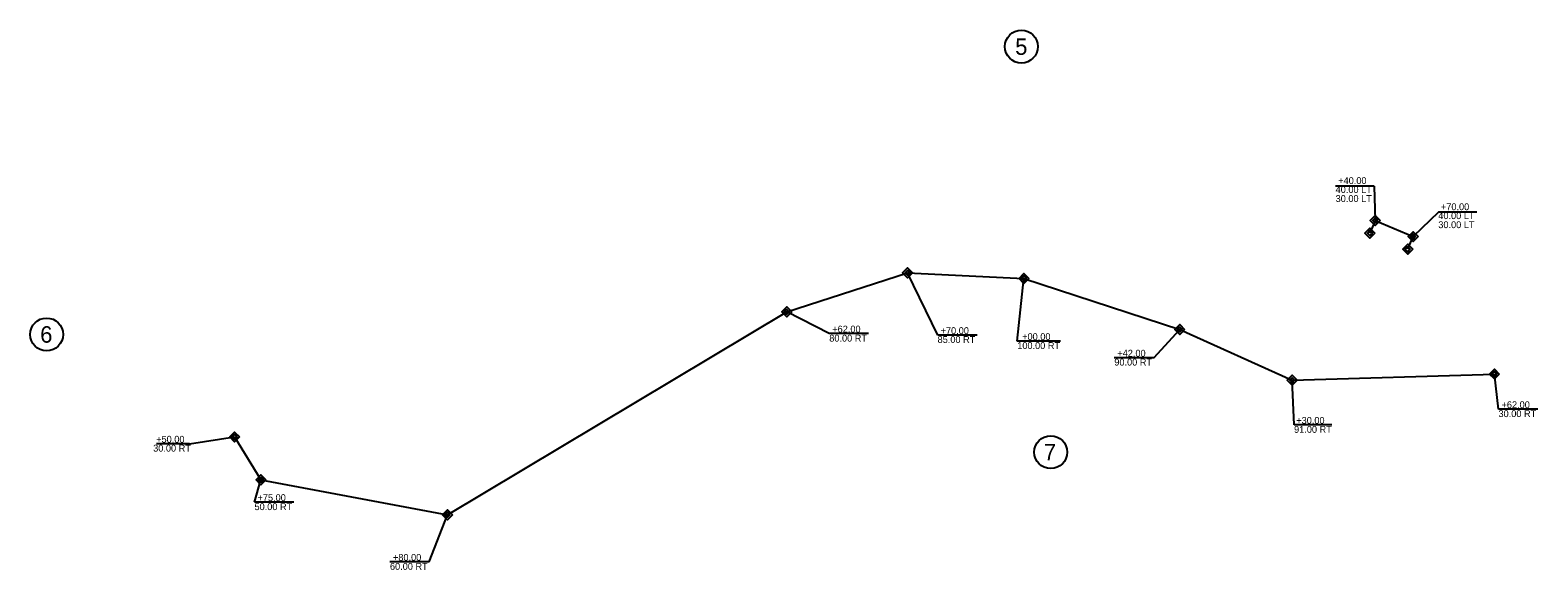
# Model space of a CAD drawing. Extents: x 1002576 to 1014655, y 551673 to 557994.
# Drawn here: x 1010654 to 1011753, y 551946 to 552340 of the extents above; entities that cross this region are included whole.
import ezdxf

# ---------------------------------------------------------------- set-up
doc = ezdxf.new("R2010")
doc.units = 0
for name, color, linetype in [('Exist Hydro Stream or Body of Water', 7, 'Continuous'), ('Exist Other Culture Area Outline', 7, 'Continuous'), ('Exist Roads EOP Other', 7, 'Continuous'), ('Exist Structure Major Deck Tunnel Box Culvert', 7, 'Continuous'), ('Exist Utilities Power Pole CELL', 7, 'Continuous')]:
    doc.layers.add(name, color=color, linetype=linetype)

msp = doc.modelspace()

# ---------------------------------------------------------------- linework, layer by layer
at = {"layer": 'Exist Hydro Stream or Body of Water'}
for p, q in [((1011634.9, 552201.4), (1011634.9, 552201.4)), ((1011631, 552192.2), (1011631, 552192.2)), ((1011662.5, 552189.6), (1011662.5, 552189.6)), ((1011658.6, 552180.4), (1011658.6, 552180.4)), ((1011293.8, 552163.2), (1011293.8, 552163.2)), ((1011378.7, 552159.1), (1011378.7, 552159.1)), ((1011205.7, 552134.7), (1011205.7, 552134.7)), ((1011492.3, 552121.8), (1011492.3, 552121.8)), ((1011574.3, 552084.8), (1011574.3, 552084.8)), ((1011721.8, 552089.3), (1011721.8, 552089.3)), ((1010803, 552043.4), (1010803, 552043.4)), ((1010822.2, 552012.1), (1010822.2, 552012.1)), ((1010958.2, 551986.6), (1010958.2, 551986.6))]:
    msp.add_line(p, q, dxfattribs=at)
at = {"layer": 'Exist Other Culture Area Outline'}
for p, q in [((1011634.9, 552201.4), (1011631, 552192.2)), ((1011634.9, 552201.4), (1011662.5, 552189.6)), ((1011658.6, 552180.4), (1011662.5, 552189.6)), ((1011205.7, 552134.7), (1011293.8, 552163.2)), ((1011293.8, 552163.2), (1011378.7, 552159.1)), ((1011378.7, 552159.1), (1011492.3, 552121.8)), ((1010958.2, 551986.6), (1011205.7, 552134.7)), ((1011492.3, 552121.8), (1011574.3, 552084.8)), ((1011574.3, 552084.8), (1011721.8, 552089.3)), ((1010803, 552043.4), (1010822.2, 552012.1)), ((1010822.2, 552012.1), (1010958.2, 551986.6))]:
    msp.add_line(p, q, dxfattribs=at)
at = {"layer": 'Exist Roads EOP Other'}
for p, q in [((1011634.1, 552226.5), (1011606, 552226.5)), ((1011709.1, 552207.4), (1011681, 552207.4)), ((1011265.4, 552118.8), (1011236.7, 552118.8)), ((1011344.5, 552117.8), (1011315.8, 552117.8)), ((1011405.3, 552113.3), (1011373.8, 552113.3)), ((1011473.3, 552101.2), (1011444.6, 552101.2)), ((1011753.5, 552063.7), (1011724.8, 552063.7)), ((1011603.2, 552052.2), (1011575.7, 552052.2)), ((1010770, 552038.4), (1010746, 552038.4)), ((1010846.2, 551995.8), (1010817.5, 551995.8)), ((1010945, 551952.2), (1010916.3, 551952.2))]:
    msp.add_line(p, q, dxfattribs=at)
for points in [[(1011634.1, 552226.5), (1011634.9, 552201.4)], [(1011681, 552207.4), (1011662.5, 552189.6)], [(1011315.8, 552117.8), (1011293.8, 552163.2)], [(1011373.8, 552113.3), (1011378.7, 552159.1)], [(1011236.7, 552118.8), (1011205.7, 552134.7)], [(1011473.3, 552101.2), (1011492.3, 552121.8)], [(1011575.7, 552052.2), (1011574.3, 552084.8)], [(1011724.8, 552063.7), (1011721.8, 552089.3)], [(1010770, 552038.4), (1010803, 552043.4)], [(1010817.5, 551995.8), (1010822.2, 552012.1)], [(1010945, 551952.2), (1010958.2, 551986.6)]]:
    msp.add_lwpolyline(points, dxfattribs=at)
at = {"layer": 'Exist Structure Major Deck Tunnel Box Culvert'}
for points in [[(1011638.5, 552201.4), (1011634.9, 552197.8), (1011631.3, 552201.4), (1011634.9, 552205)], [(1011634.6, 552192.2), (1011631, 552188.6), (1011627.4, 552192.2), (1011631, 552195.8)], [(1011636.7, 552201.4), (1011634.9, 552199.6), (1011633.1, 552201.4), (1011634.9, 552203.2)], [(1011632.8, 552192.2), (1011631, 552190.4), (1011629.2, 552192.2), (1011631, 552194)], [(1011662.2, 552180.4), (1011658.6, 552176.8), (1011655, 552180.4), (1011658.6, 552184)], [(1011666.1, 552189.6), (1011662.5, 552186), (1011658.9, 552189.6), (1011662.5, 552193.2)], [(1011664.3, 552189.6), (1011662.5, 552187.8), (1011660.7, 552189.6), (1011662.5, 552191.4)], [(1011660.4, 552180.4), (1011658.6, 552178.6), (1011656.8, 552180.4), (1011658.6, 552182.2)], [(1011297.4, 552163.2), (1011293.8, 552159.6), (1011290.2, 552163.2), (1011293.8, 552166.8)], [(1011295.6, 552163.2), (1011293.8, 552161.4), (1011292, 552163.2), (1011293.8, 552165)], [(1011382.3, 552159.1), (1011378.7, 552155.5), (1011375.1, 552159.1), (1011378.7, 552162.7)], [(1011380.5, 552159.1), (1011378.7, 552157.3), (1011376.9, 552159.1), (1011378.7, 552160.9)], [(1011209.3, 552134.7), (1011205.7, 552131.1), (1011202.1, 552134.7), (1011205.7, 552138.3)], [(1011207.5, 552134.7), (1011205.7, 552132.9), (1011203.9, 552134.7), (1011205.7, 552136.5)], [(1011495.9, 552121.8), (1011492.3, 552118.2), (1011488.7, 552121.8), (1011492.3, 552125.4)], [(1011494.1, 552121.8), (1011492.3, 552120), (1011490.5, 552121.8), (1011492.3, 552123.6)], [(1011577.9, 552084.8), (1011574.3, 552081.2), (1011570.7, 552084.8), (1011574.3, 552088.4)], [(1011576.1, 552084.8), (1011574.3, 552083), (1011572.5, 552084.8), (1011574.3, 552086.6)], [(1011725.4, 552089.3), (1011721.8, 552085.7), (1011718.2, 552089.3), (1011721.8, 552092.9)], [(1011723.6, 552089.3), (1011721.8, 552087.5), (1011720, 552089.3), (1011721.8, 552091.1)], [(1010806.6, 552043.4), (1010803, 552039.8), (1010799.4, 552043.4), (1010803, 552047)], [(1010804.8, 552043.4), (1010803, 552041.6), (1010801.2, 552043.4), (1010803, 552045.2)], [(1010825.8, 552012.1), (1010822.2, 552008.5), (1010818.6, 552012.1), (1010822.2, 552015.7)], [(1010824, 552012.1), (1010822.2, 552010.3), (1010820.4, 552012.1), (1010822.2, 552013.9)], [(1010961.8, 551986.6), (1010958.2, 551983), (1010954.6, 551986.6), (1010958.2, 551990.2)], [(1010960, 551986.6), (1010958.2, 551984.8), (1010956.4, 551986.6), (1010958.2, 551988.4)]]:
    msp.add_lwpolyline(points, close=True, dxfattribs=at)
at = {"layer": 'Exist Utilities Power Pole CELL'}
for p, q in [((1011376.8, 552328.3), (1011376.8, 552328.3)), ((1010665.9, 552118.2), (1010665.9, 552118.2)), ((1011398.2, 552032.3), (1011398.2, 552032.3))]:
    msp.add_line(p, q, dxfattribs=at)
for centre in [(1011376.8, 552328.3), (1010665.9, 552118.2), (1011398.2, 552032.3)]:
    msp.add_circle(centre, 12, dxfattribs=at)

# ---------------------------------------------------------------- texts
at = {"layer": 'Exist Roads EOP Other'}
for s, p in [('+40.00', (1011607.9, 552228)), ('40.00 LT', (1011606, 552221.5)), ('30.00 LT', (1011606, 552214.9)), ('40.00 LT', (1011680.9, 552202.4)), ('+70.00', (1011682.8, 552208.9)), ('30.00 LT', (1011680.9, 552195.8)), ('80.00 RT', (1011236.7, 552113)), ('+62.00', (1011238.9, 552119.6)), ('85.00 RT', (1011315.7, 552112)), ('+70.00', (1011317.9, 552118.5)), ('+00.00', (1011377.4, 552114.1)), ('100.00 RT', (1011373.8, 552107.6)), ('+42.00', (1011446.8, 552102)), ('90.00 RT', (1011444.6, 552095.5)), ('30.00 RT', (1011724.8, 552057.9)), ('+62.00', (1011727, 552064.4)), ('91.00 RT', (1011575.7, 552046.4)), ('+30.00', (1011577.3, 552053)), ('+50.00', (1010745.8, 552039.2)), ('30.00 RT', (1010743.6, 552032.7)), ('+75.00', (1010819.7, 551996.6)), ('50.00 RT', (1010817.5, 551990)), ('+80.00', (1010918.5, 551953)), ('60.00 RT', (1010916.3, 551946.4))]:
    msp.add_text(s, height=5, dxfattribs=at).set_placement(p)
at = {"layer": 'Exist Utilities Power Pole CELL'}
for s, p in [('5', (1011372.3, 552322.3)), ('6', (1010661.2, 552112.2)), ('7', (1011393.2, 552026.3))]:
    msp.add_text(s, height=12, dxfattribs=at).set_placement(p)

doc.saveas('drawing.dxf')
